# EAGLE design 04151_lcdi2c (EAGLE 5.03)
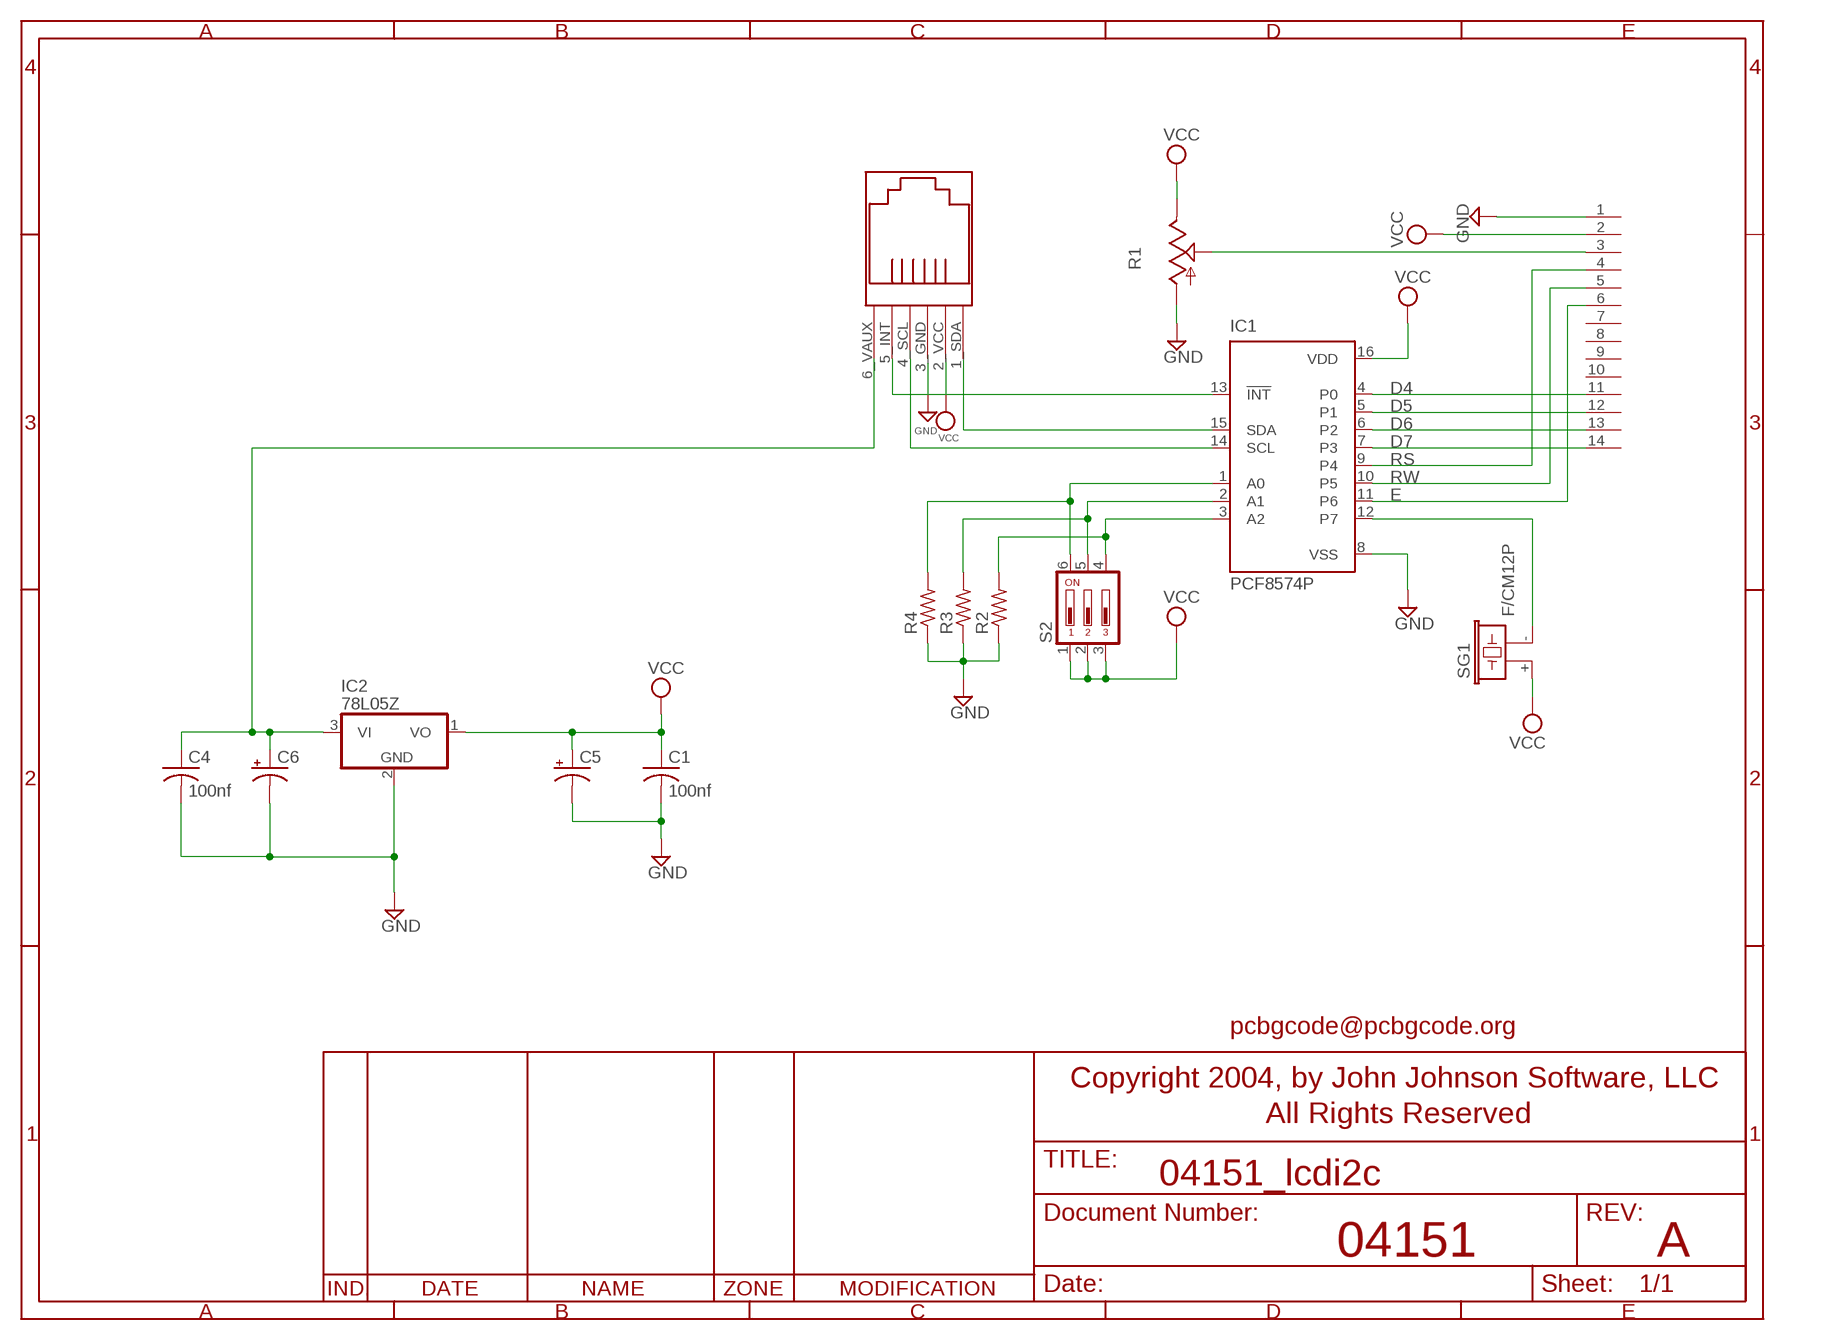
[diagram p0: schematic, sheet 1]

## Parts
C1  100nf  C-US025-025X050  [C025-025X050]
C4  100nf  C-US025-025X050  [C025-025X050]
C5  CPOL-US!FAT_E2,5-5  [!FAT_E2,5-5]
C6  CPOL-US!FAT_E2,5-5  [!FAT_E2,5-5]
IC1  PCF8574P  [DIL16]
IC2  78L05Z  [TO92]
R1  TRIM_US-PT-SPIN  [PT-SPIN]
R2  R-US_0204/5  [0204/5]
R3  R-US_0204/5  [0204/5]
R4  R-US_0204/5  [0204/5]
S2  DIP03YL  [DIP03YL]
SG1  F/CM12P  [F/CM12P]
U$1  RJ-12  [RJ-12]
U$2  MA07-2-SGL  [MA07-2]

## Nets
D4: IC1.4(P0) U$2.11
D5: IC1.5(P1) U$2.12
D6: IC1.6(P2) U$2.13
D7: IC1.7(P3) U$2.14
E: IC1.11(P6) U$2.6
GND: C1.2 C4.2 C5.P$2(-) C6.P$2(-) IC1.8(VSS) IC2.2(GND) R1.A R2.1 R3.1 R4.1 U$1.3_GND U$2.1
N$1: R1.S U$2.3
N$2: IC1.3(A2) R2.2 S2.4
N$3: IC1.2(A1) R3.2 S2.5
N$4: IC1.1(A0) R4.2 S2.6
N$5: IC1.13(!INT) U$1.5_INT
N$7: IC1.15(SDA) U$1.1_SDA
N$8: IC1.12(P7) SG1.-
N$9: IC1.14(SCL) U$1.4_SCL
N$12: C4.1 C6.P$1(+) IC2.3(VI) U$1.6_VAUX
RS: IC1.9(P4) U$2.4
RW: IC1.10(P5) U$2.5
VCC: C1.1 C5.P$1(+) IC1.16(VDD) IC2.1(VO) R1.E S2.1 S2.2 S2.3 SG1.+ U$1.2_VCC U$2.2
Unconnected: U$2.7 U$2.8 U$2.9 U$2.10

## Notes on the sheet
- pcbgcode@pcbgcode.org
- 04151 | A

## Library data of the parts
C1 C4 = rcl:C-US: CAPACITOR, American symbol
C5 C6 = rcl:CPOL-US: POLARIZED CAPACITOR, American symbol
IC1 = micro-philips:PCF8574: I2C-Bus I/O DEVICE
IC2 = linear:78*: Positive VOLTAGE REGULATOR
R1 = pot:TRIM_US-: POTENTIOMETER
R2-R4 = rcl:R-US_: RESISTOR, American symbol
S2 = switch-dil:DIP03YL: DIL/CODE SWITCH
SG1 = buzzer:F/CM12P: BUZZER
U$1 = con-rj:RJ-12
U$2 = con-lstb:MA07-2-SGL

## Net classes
0 default: width 0.406 mm

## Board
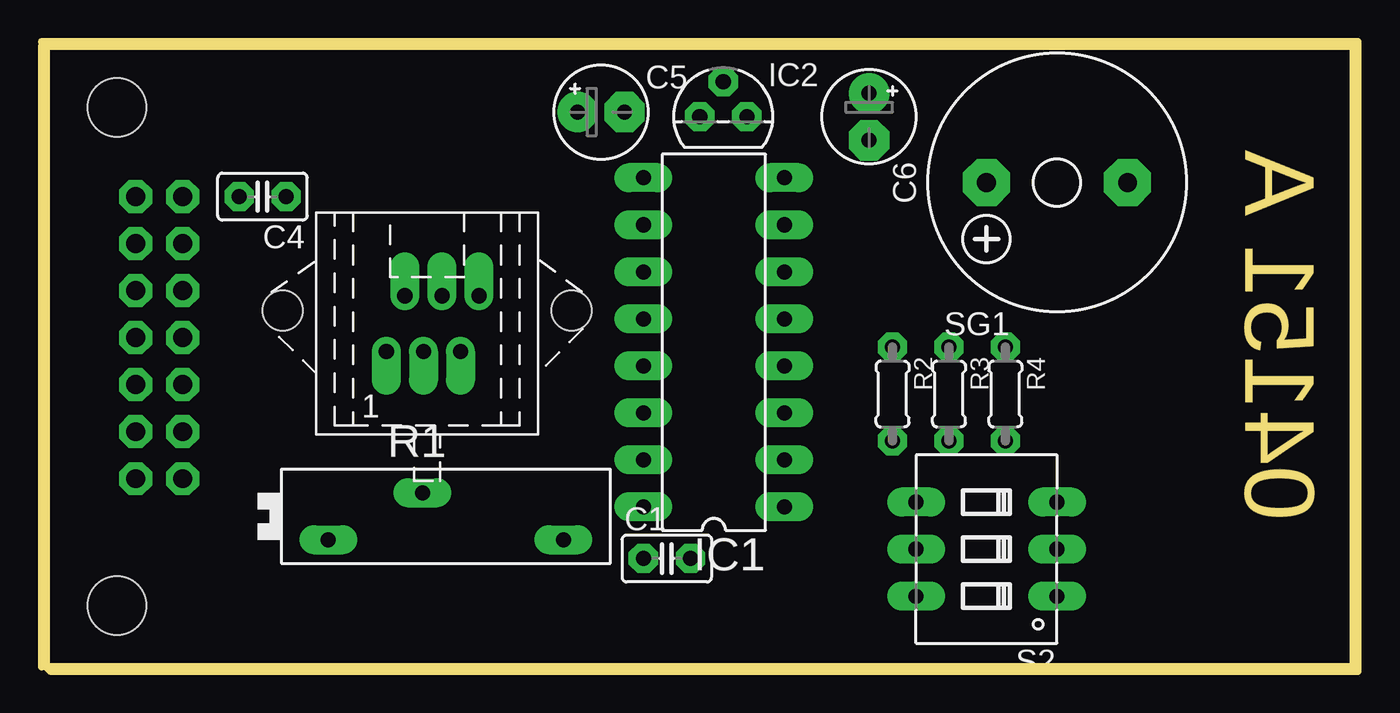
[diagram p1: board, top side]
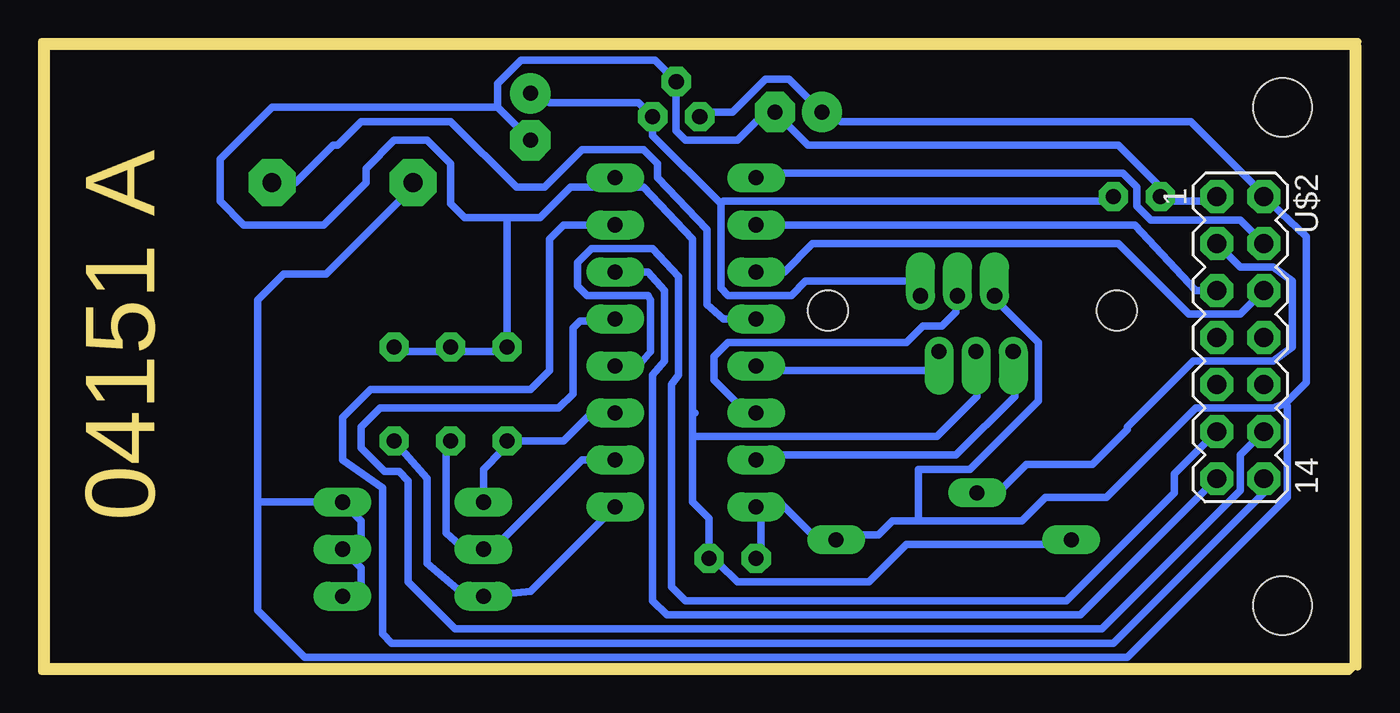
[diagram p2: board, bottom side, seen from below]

Size 70.61 x 33.53 mm. Coordinates in mm from the lower left corner, seen from the top.
Outline: 0,0 70.61,0 70.61,33.53 0,33.53 0,0
Copper layers (1*16): Top 0.035mm / dielectric 1.5mm / Bottom 0.035mm
Design rules "default": minimum track width 16mil, minimum drill 24mil, track to track 10mil, track to pad 5mil, pad to pad 10mil, via to via 10mil, smd to smd 10mil, copper to edge 0mil, drill to drill 8mil, minimum pad ring 10mil, minimum via ring 30mil, stop-mask expansion 4mil, vias tented up to drill 0mil, thermal gap 16mil
Holes 3.17 mm at 3.81,30.23 3.81,3.3
Milling: 5 lines

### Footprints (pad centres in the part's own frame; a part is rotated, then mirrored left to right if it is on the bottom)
C025-025X050 = drill 0.813 octagon: 1 -1.27,0; 2 1.27,0
!FAT_E2,5-5 = drill 0.813 pad 2.184 round: P$1 -1.27,0 | drill 0.813 pad 2.184 octagon: P$2 1.27,0
DIL16 = drill 0.813 long: 1 -8.89,-3.81; 2 -6.35,-3.81; 3 -3.81,-3.81; 4 -1.27,-3.81; 5 1.27,-3.81; 6 3.81,-3.81; 7 6.35,-3.81; 8 8.89,-3.81; 9 8.89,3.81; 10 6.35,3.81; 11 3.81,3.81; 12 1.27,3.81; 13 -1.27,3.81; 14 -3.81,3.81; 15 -6.35,3.81; 16 -8.89,3.81
TO92 = drill 0.813 octagon: 1 -1.27,0; 2 0,1.905; 3 1.27,0
PT-SPIN = drill 0.813 long: A -6.35,-1.27; E 6.35,-1.27; S -1.27,1.27
0204/5 = drill 0.813 octagon: 1 -2.54,0; 2 2.54,0
DIP03YL = drill 0.813 long: 1 -2.54,-3.81; 2 0,-3.81; 3 2.54,-3.81; 4 2.54,3.81; 5 0,3.81; 6 -2.54,3.81
F/CM12P = drill 1.016 pad 2.54 octagon: + 3.81,0; - -3.81,0
RJ-12 = drill 0.813 offset: 1_SDA 2.2,1.5; 2_VCC 1.2,-1.5; 3_GND 0.2,1.5; 4_SCL -0.8,-1.5; 5_INT -1.8,1.5; 6_VAUX -2.8,-1.5 | hole 2.184: -7.8,-0.7; 7.8,-0.7
MA07-2 = drill 1.016 octagon: 1 -7.62,-1.27; 2 -7.62,1.27; 3 -5.08,-1.27; 4 -5.08,1.27; 5 -2.54,-1.27; 6 -2.54,1.27; 7 0,-1.27; 8 0,1.27; 9 2.54,-1.27; 10 2.54,1.27; 11 5.08,-1.27; 12 5.08,1.27; 13 7.62,-1.27; 14 7.62,1.27

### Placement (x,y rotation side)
C1  33.53,5.84 0 top
C4  11.68,25.4 180 top
C5  29.97,29.97 0 top
C6  44.45,29.72 270 top
IC1  36.07,17.53 90 top
IC2  36.58,29.72 0 top
R1  21.59,8.13 0 top
R2  45.72,14.73 270 top
R3  48.77,14.73 270 top
R4  51.82,14.73 270 top
S2  50.8,6.35 90 top
SG1  54.61,26.16 180 top
U$1  20.57,18.54 180 top
U$2  6.1,17.78 270 bottom

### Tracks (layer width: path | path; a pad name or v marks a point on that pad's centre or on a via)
D4
  Bottom 0.406: IC1.4 38.61,16.26 37.97,17.02 37.97,19.81 38.1,20.07 41.4,20.07 41.91,20.57 41.91,21.84 41.15,22.61 37.85,22.61 36.45,21.08 36.45,15.75 36.83,15.24 36.83,4.32 36.07,3.56 15.49,3.56 9.65,9.4 9.65,10.41 U$2.11
D5
  Bottom 0.406: U$2.12 6.1,11.43 6.1,9.53 13.59,2.03 48.51,2.03 51.05,4.57 51.05,10.03 51.56,10.54 52.32,10.54 53.59,11.81 53.59,12.95 52.58,13.97 42.93,13.97 42.16,14.73 42.16,18.29 41.78,18.67 41.15,18.67 41.08,18.61 | IC1.5 40.89,18.8 41.08,18.61 | 41.08,18.61 41.15,18.54
D6
  Bottom 0.406: U$2.13 14.73,2.79 37.08,2.79 37.85,3.56 37.85,15.75 37.21,16.51 37.21,20.32 38.1,21.34 IC1.6
D7
  Bottom 0.406: U$2.14 4.83,9.4 12.95,1.27 51.94,1.27 52.45,1.78 52.45,9.65 54.61,11.18 54.61,13.46 53.09,14.99 44.45,14.99 43.43,16 43.43,23.11 42.67,23.88 IC1.7
E
  Bottom 0.406: U$2.6 6.1,19.05 8.89,19.05 12.7,22.86 29.21,22.86 30.73,21.34 IC1.11 32.38,21.34
GND
  Bottom 0.406: R1.A 16.51,6.6 24.13,6.6 26.16,4.57 33.27,4.57 34.29,5.59 C1.2 34.8,8 35.69,8.89 35.69,12.45 | R4.1 51.31,17.02 49.28,17.02 R3.1 48.26,17.02 46.23,17.02 R2.1 45.72,24.26 | U$2.1 7.87,25.15 9.91,25.15 C4.2 10.41,25.91 12.7,28.19 29.46,28.19 C5.P$2 32.26,29.46 33.27,28.45 36.07,28.45 36.58,28.96 IC2.2 37.72,32.77 44.96,32.77 46.23,31.5 46.23,30.23 | 46.23,30.23 C6.P$2 | 46.23,30.23 58.42,30.23 61.21,27.43 61.21,25.15 59.94,23.88 55.63,23.88 53.34,26.16 53.34,26.92 51.82,28.45 50.04,28.45 48.77,27.18 48.77,25.02 48.01,24.26 45.72,24.26 | U$1.3_GND 20.34,17.04 20.32,17.02 20.32,14.61 22.48,12.45 35.69,12.45 | 35.69,12.45 35.69,13.59 35.56,13.72 35.69,13.72 35.69,23.11 38.35,25.91 39.37,25.91 IC1.8 40.39,25.91 42.29,25.91 43.94,24.26 45.72,24.26
N$1
  Bottom 0.406: R1.S 19.05,9.65 18.92,9.65 17.65,10.92 14.1,10.92 12.19,12.83 12.19,12.95 8.64,16.51 4.32,16.51 3.3,17.27 3.3,20.83 4.32,21.59 6.1,21.59 U$2.3
N$2
  Bottom 0.406: 45.77,12.09 45.97,11.68 46.99,10.67 S2.4 | 45.77,12.09 R2.2 | IC1.3 41.15,13.72 42.67,12.19 45.97,12.19 45.87,12.09 45.77,12.09
N$3
  Bottom 0.406: IC1.2 41.66,11.18 46.23,6.6 S2.5 48.01,6.35 49.02,7.24 49.02,12.19 R3.2
N$4
  Bottom 0.406: S2.6 47.24,4.06 | IC1.1 44.45,4.06 S2.6 | S2.6 48.26,4.06 50.04,5.59 50.04,10.16 R4.2
N$5
  Bottom 0.406: IC1.13 30.99,16 22.86,16 U$1.5_INT
N$7
  Bottom 0.406: IC1.15 30.99,11.43 21.46,11.43 18.29,14.61 18.29,17.02 18.31,17.04 U$1.1_SDA
N$8
  Bottom 0.406: IC1.12 34.04,18.8 34.92,19.56 34.92,23.62 37.59,26.42 37.59,27.18 38.35,27.94 41.66,27.94 43.69,25.91 45.21,25.91 48.77,29.46 53.59,29.46 54.86,28.19 55.12,28.19 57.15,26.16 SG1.-
N$9
  Bottom 0.406: IC1.14 32.77,13.72 34.54,15.49 34.54,16.76 33.78,17.53 24.13,17.53 23.24,18.41 22.23,18.41 21.46,19.18 21.46,19.94 21.37,20.03 U$1.4_SCL
N$12
  Bottom 0.406: 23.88,20.83 U$1.6_VAUX | C4.1 13.46,25.15 34.04,25.15 34.16,25.02 | C6.P$1 43.43,30.48 38.61,30.48 IC2.3 37.85,28.7 34.16,25.02 | 34.16,25.02 34.16,20.45 33.78,20.07 30.35,20.07 29.59,20.83 23.88,20.83 | 23.88,20.83 23.75,20.95
RS
  Bottom 0.406: IC1.9 30.99,26.67 12.45,26.67 11.68,25.91 11.68,24.89 10.92,24.13 6.1,24.13 U$2.4
RW
  Bottom 0.406: IC1.10 11.81,23.88 8.51,20.32 U$2.5
VCC
  Bottom 0.406: S2.1 53.59,3.81 53.59,5.33 S2.2 53.59,6.35 53.59,7.87 S2.3 59.18,8.89 | SG1.+ 51.56,25.15 55.5,21.21 57.78,21.21 59.18,19.81 59.18,8.89 | U$1.2_VCC 19.05,19.56 17.02,17.53 17.02,14.35 20.7,10.67 23.5,10.67 23.5,8 23.62,7.87 | C1.1 32,6.35 32,8.13 IC1.16 30.99,8.89 29.21,7.11 R1.E 26.67,7.11 25.65,7.11 24.89,7.87 23.62,7.87 | 3.68,14.22 2.54,15.37 2.54,23.24 U$2.2 5.33,25.91 5.33,26.04 8.76,29.46 27.69,29.46 C5.P$1 30.48,31.75 31.75,31.75 33.53,29.97 35.05,29.97 IC2.1 | 3.68,14.22 4.32,13.97 8.51,13.97 13.34,9.14 16.64,9.14 17.91,7.87 23.62,7.87 | 3.68,14.22 3.56,14.1 3.56,9.14 12.19,0.51 56.64,0.51 59.18,3.05 59.18,8.89

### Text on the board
Milling: 04151 A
